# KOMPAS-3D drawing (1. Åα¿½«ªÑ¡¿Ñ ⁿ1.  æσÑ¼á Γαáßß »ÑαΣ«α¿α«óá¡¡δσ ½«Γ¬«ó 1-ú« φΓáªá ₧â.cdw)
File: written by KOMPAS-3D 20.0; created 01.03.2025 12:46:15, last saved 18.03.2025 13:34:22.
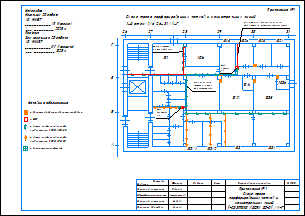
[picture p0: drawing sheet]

Sheet 1: A4, landscape

Document properties: Автор: user; Полное имя файла: \\Storage\20 Отдел\Мои документы\Крашенинников Е\ТЗ 1й этаж юг\Приложение  Схема трасс перфорированных лотков 1-го этажа ЮГ.cdw

Title block, sheet 1: scale: 1:1; Количество листов документа: 1; Форматы листов документа: A4

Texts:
  Условные обозначения:
  - Пластиковый распределительный бокс
  - ШСР
  - Лоток перфорированный с
  разделителем 3000х200х50
  разделителем 3000х100х50
  - Коммутационный шкаф
  Утверждаю
  Начальник 20 отдела
  АО "НИИЭТ"
  Зам. начальника 20 отдела
  Схема трасс перфорированных лотков и магистральных линий
  Приложение №1
  Составил
  Фамилия
  Подпись
  Дата
  Наименование планировки
  Инженер 2 категории
  Иванова
  Схема трасс
  перфорированных лотков и
  магистральных линий
  1-го этажа в осях 26-31 /А-Г
  Ведущий инженер-энергетик
  Крашенинников
  Дибров
  Начальник 18 отдела
  Крюков
  ШСР
  Вводной кабель ВВГ нг(А)LS 5x50 для
  ШСР 1 этаж Юг, монтаж силами заказчика
  ТП 5х50 от ТП8
  п. 5. ф3 к ШСР 101а
  ВВГ нг(А)LS 5x95
  от ТП8 п. 2. ф2 к
  ШСР 1-1й этаж Юг
  cacwq
  Боксы
  Стили документа
  Без основной надписи.
Dimensions and other numbers on the sheet: 101; 101а; 102а; 102б; 102в; 103; 101б; 101г; 101в; 103а; 103б; 103в; 1-й этаж в/о 26-31/А-Г; 103/1; 103/2; 1 этаж; 27; 28; 29; 30; 31; 26; 1-1 этаж; 1:1; 1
